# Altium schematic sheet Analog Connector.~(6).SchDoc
size A
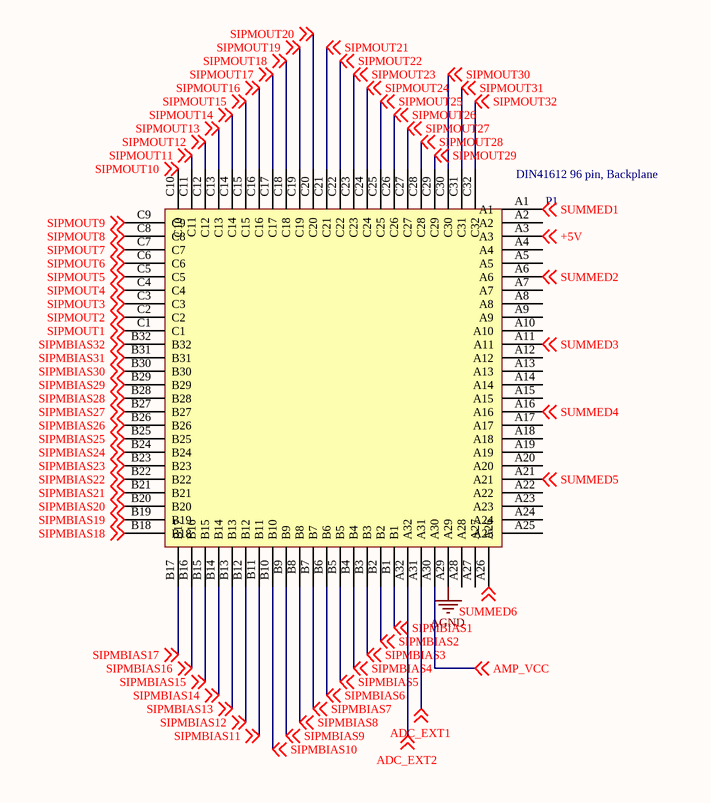
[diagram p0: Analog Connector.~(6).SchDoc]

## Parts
P1  DIN41612 96 pin, Backplane  [EURO2.54-2V96]

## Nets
AGND: P1.A29
+5V: P1.A3 ; off-sheet +5V
ADC_EXT1: P1.A31 ; off-sheet ADC_EXT1
ADC_EXT2: P1.A32 ; off-sheet ADC_EXT2
AMP_VCC: P1.A30 ; off-sheet AMP_VCC
SIPMBIAS1: P1.B1 ; off-sheet SIPMBIAS1
SIPMBIAS2: P1.B2 ; off-sheet SIPMBIAS2
SIPMBIAS3: P1.B3 ; off-sheet SIPMBIAS3
SIPMBIAS4: P1.B4 ; off-sheet SIPMBIAS4
SIPMBIAS5: P1.B5 ; off-sheet SIPMBIAS5
SIPMBIAS6: P1.B6 ; off-sheet SIPMBIAS6
SIPMBIAS7: P1.B7 ; off-sheet SIPMBIAS7
SIPMBIAS8: P1.B8 ; off-sheet SIPMBIAS8
SIPMBIAS9: P1.B9 ; off-sheet SIPMBIAS9
SIPMBIAS10: P1.B10 ; off-sheet SIPMBIAS10
SIPMBIAS11: P1.B11 ; off-sheet SIPMBIAS11
SIPMBIAS12: P1.B12 ; off-sheet SIPMBIAS12
SIPMBIAS13: P1.B13 ; off-sheet SIPMBIAS13
SIPMBIAS14: P1.B14 ; off-sheet SIPMBIAS14
SIPMBIAS15: P1.B15 ; off-sheet SIPMBIAS15
SIPMBIAS16: P1.B16 ; off-sheet SIPMBIAS16
SIPMBIAS17: P1.B17 ; off-sheet SIPMBIAS17
SIPMBIAS18: P1.B18 ; off-sheet SIPMBIAS18
SIPMBIAS19: P1.B19 ; off-sheet SIPMBIAS19
SIPMBIAS20: P1.B20 ; off-sheet SIPMBIAS20
SIPMBIAS21: P1.B21 ; off-sheet SIPMBIAS21
SIPMBIAS22: P1.B22 ; off-sheet SIPMBIAS22
SIPMBIAS23: P1.B23 ; off-sheet SIPMBIAS23
SIPMBIAS24: P1.B24 ; off-sheet SIPMBIAS24
SIPMBIAS25: P1.B25 ; off-sheet SIPMBIAS25
SIPMBIAS26: P1.B26 ; off-sheet SIPMBIAS26
SIPMBIAS27: P1.B27 ; off-sheet SIPMBIAS27
SIPMBIAS28: P1.B28 ; off-sheet SIPMBIAS28
SIPMBIAS29: P1.B29 ; off-sheet SIPMBIAS29
SIPMBIAS30: P1.B30 ; off-sheet SIPMBIAS30
SIPMBIAS31: P1.B31 ; off-sheet SIPMBIAS31
SIPMBIAS32: P1.B32 ; off-sheet SIPMBIAS32
SIPMOUT1: P1.C1 ; off-sheet SIPMOUT1
SIPMOUT2: P1.C2 ; off-sheet SIPMOUT2
SIPMOUT3: P1.C3 ; off-sheet SIPMOUT3
SIPMOUT4: P1.C4 ; off-sheet SIPMOUT4
SIPMOUT5: P1.C5 ; off-sheet SIPMOUT5
SIPMOUT6: P1.C6 ; off-sheet SIPMOUT6
SIPMOUT7: P1.C7 ; off-sheet SIPMOUT7
SIPMOUT8: P1.C8 ; off-sheet SIPMOUT8
SIPMOUT9: P1.C9 ; off-sheet SIPMOUT9
SIPMOUT10: P1.C10 ; off-sheet SIPMOUT10
SIPMOUT11: P1.C11 ; off-sheet SIPMOUT11
SIPMOUT12: P1.C12 ; off-sheet SIPMOUT12
SIPMOUT13: P1.C13 ; off-sheet SIPMOUT13
SIPMOUT14: P1.C14 ; off-sheet SIPMOUT14
SIPMOUT15: P1.C15 ; off-sheet SIPMOUT15
SIPMOUT16: P1.C16 ; off-sheet SIPMOUT16
SIPMOUT17: P1.C17 ; off-sheet SIPMOUT17
SIPMOUT18: P1.C18 ; off-sheet SIPMOUT18
SIPMOUT19: P1.C19 ; off-sheet SIPMOUT19
SIPMOUT20: P1.C20 ; off-sheet SIPMOUT20
SIPMOUT21: P1.C21 ; off-sheet SIPMOUT21
SIPMOUT22: P1.C22 ; off-sheet SIPMOUT22
SIPMOUT23: P1.C23 ; off-sheet SIPMOUT23
SIPMOUT24: P1.C24 ; off-sheet SIPMOUT24
SIPMOUT25: P1.C25 ; off-sheet SIPMOUT25
SIPMOUT26: P1.C26 ; off-sheet SIPMOUT26
SIPMOUT27: P1.C27 ; off-sheet SIPMOUT27
SIPMOUT28: P1.C28 ; off-sheet SIPMOUT28
SIPMOUT29: P1.C29 ; off-sheet SIPMOUT29
SIPMOUT30: P1.C30 ; off-sheet SIPMOUT30
SIPMOUT31: P1.C31 ; off-sheet SIPMOUT31
SIPMOUT32: P1.C32 ; off-sheet SIPMOUT32
SUMMED1: P1.A1 ; off-sheet SUMMED1
SUMMED2: P1.A6 ; off-sheet SUMMED2
SUMMED3: P1.A11 ; off-sheet SUMMED3
SUMMED4: P1.A16 ; off-sheet SUMMED4
SUMMED5: P1.A21 ; off-sheet SUMMED5
SUMMED6: P1.A26 ; off-sheet SUMMED6

Not connected (* = marked no-connect by the designer): P1 A2 A4 A5 A7 A8 A9 A10 A12 A13 A14 A15 A17 A18 A19 A20 A22 A23 A24 A25 A27 A28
